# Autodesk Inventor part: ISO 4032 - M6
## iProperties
Comments: To add or edit properties for Autodesk Inventor files, use iProperties.
Created: 2004-08
Part Number: ISO 4032 - M6
Vendor: Autodesk Inc.
Document SubType Name: Modeling
Designer: John Blackburn
Material: Default
Description: Hex Nut
Standard: ISO 4032
Size Designation: M6
Alert: To add or edit properties for Autodesk Inventor files, use iProperties.
Control State: 0
Master: False
Checked Out: False
Shininess: 64.0
Length Units: 11269
Angle Units: 11279
Time Units: 11290
Mass Units: 11283
Length Display Precision: 3
Angle Display Precision: 2
Compacted: True
EGR: 1
Density: 0.0
Volumn: 0.0
Area: 0.0
PropertySet Name: Model Information
Author: John Blackburn
Revision Number: 8
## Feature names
1. Body [Extrusion]
2. Chamfer1 [Revolution]
3. Thread [Hole]
4. Chamfer2
5. Chamfer3
